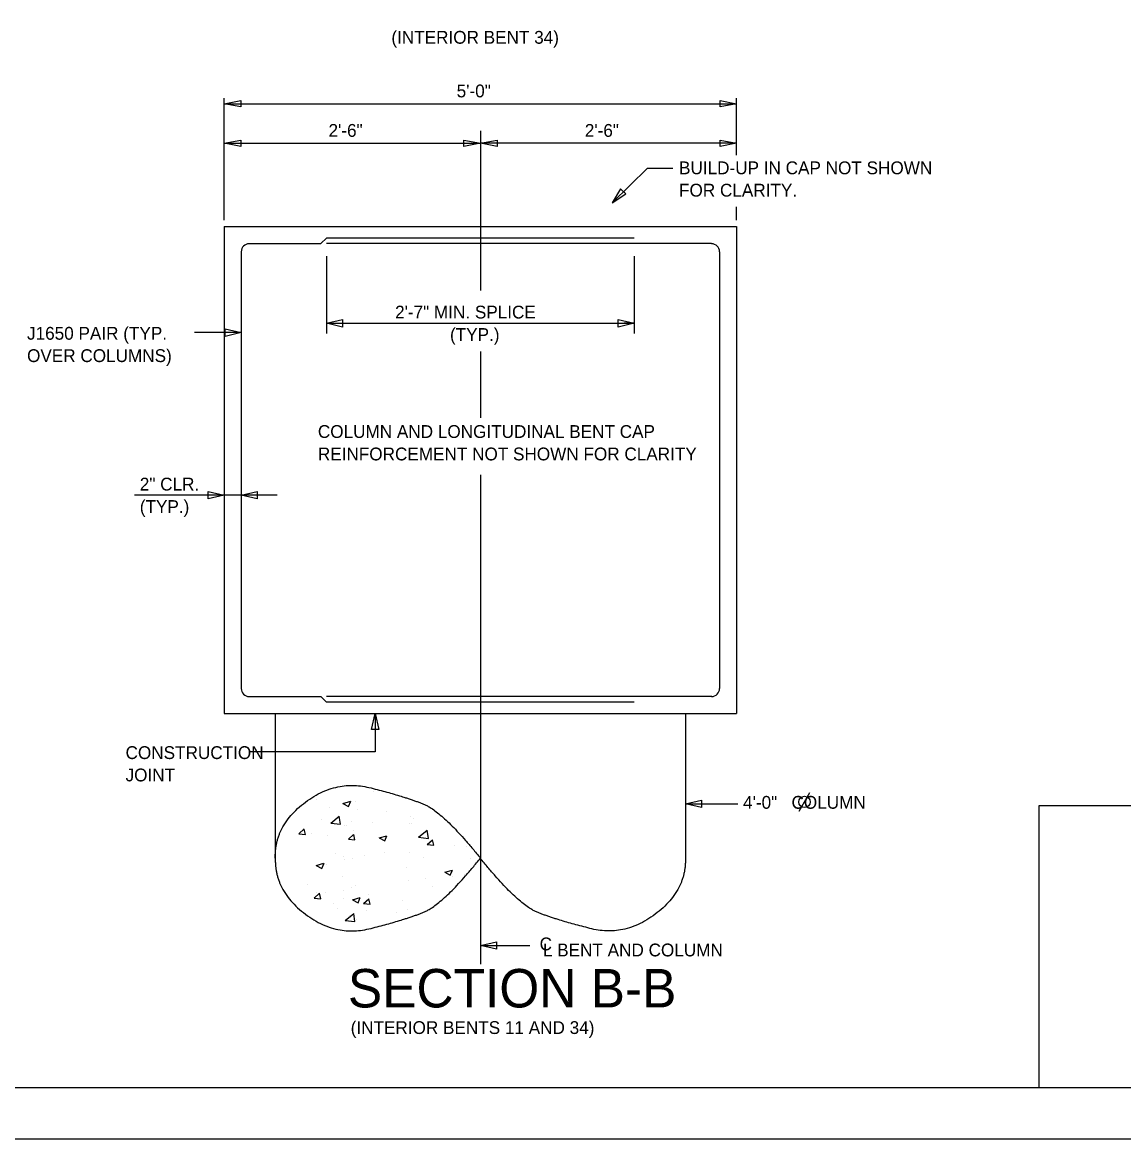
# Model space of a CAD drawing. Extents: x -133.1 to -97, y -1.7 to 20.3.
# Drawn here: x -120.43 to -109.68, y -1.69 to 9.2 of the extents above; entities that cross this region are included whole.
import ezdxf

# ---------------------------------------------------------------- set-up
doc = ezdxf.new("R2010")
doc.units = 0
for name, color, linetype in [('BR_AUTO DIMENSION', 7, 'Continuous'), ('BR_BORDER LINES', 7, 'Continuous'), ('BR_CENTER LINES', 7, 'Continuous'), ('BR_CONCRETE', 7, 'Continuous'), ('BR_REBAR', 7, 'Continuous'), ('BR_TEXT', 7, 'Continuous'), ('Level 31', 7, 'Continuous')]:
    doc.layers.add(name, color=color, linetype=linetype)

msp = doc.modelspace()

# ---------------------------------------------------------------- linework, layer by layer
at = {"layer": 'BR_AUTO DIMENSION'}
for p, q in [((-118.457, 7.268), (-118.457, 8.458)), ((-118.457, 8.403), (-113.457, 8.403)), ((-113.457, 7.903), (-113.457, 8.458)), ((-118.457, 8.018), (-115.957, 8.018)), ((-113.457, 8.018), (-115.957, 8.018)), ((-113.457, 7.268), (-113.457, 7.398)), ((-117.457, 6.918), (-117.457, 6.164)), ((-114.457, 6.918), (-114.457, 6.164)), ((-117.457, 6.262), (-114.457, 6.262)), ((-118.29, 6.171), (-118.744, 6.171)), ((-117.939, 4.586), (-119.331, 4.586)), ((-116.984, 2.455), (-116.984, 2.082)), ((-116.984, 2.082), (-118.208, 2.082)), ((-113.957, 1.576), (-113.445, 1.576)), ((-115.957, 0.192), (-115.474, 0.192))]:
    msp.add_line(p, q, dxfattribs=at)
for points in [[(-118.294, 8.372), (-118.457, 8.403), (-118.294, 8.434)], [(-113.619, 8.434), (-113.457, 8.403), (-113.619, 8.372)], [(-118.294, 7.987), (-118.457, 8.018), (-118.294, 8.05)], [(-116.119, 8.05), (-115.957, 8.018), (-116.119, 7.987)], [(-115.794, 7.987), (-115.957, 8.018), (-115.794, 8.05)], [(-113.619, 8.05), (-113.457, 8.018), (-113.619, 7.987)], [(-114.589, 7.575), (-114.671, 7.437), (-114.537, 7.525)], [(-118.446, 6.207), (-118.29, 6.171), (-118.446, 6.135)], [(-117.301, 6.226), (-117.457, 6.262), (-117.301, 6.298)], [(-114.613, 6.298), (-114.457, 6.262), (-114.613, 6.226)], [(-118.613, 4.622), (-118.457, 4.586), (-118.613, 4.55)], [(-118.134, 4.55), (-118.29, 4.586), (-118.134, 4.622)], [(-117.02, 2.299), (-116.984, 2.455), (-116.948, 2.299)], [(-113.801, 1.54), (-113.957, 1.576), (-113.801, 1.612)], [(-115.801, 0.156), (-115.957, 0.192), (-115.801, 0.228)]]:
    msp.add_lwpolyline(points, close=True, dxfattribs=at)
msp.add_lwpolyline([(-114.671, 7.437), (-114.325, 7.774), (-114.081, 7.774)], dxfattribs=at)
at = {"layer": 'BR_BORDER LINES'}
for p, q in [((-110.507, 1.559), (-105.142, 1.559)), ((-110.507, -1.191), (-110.507, 1.559)), ((-131.308, -1.191), (-97.642, -1.191))]:
    msp.add_line(p, q, dxfattribs=at)
at = {"layer": 'BR_CENTER LINES'}
for p, q in [((-115.957, 8.138), (-115.957, 6.581)), ((-115.957, 5.987), (-115.957, 5.339)), ((-115.957, 4.784), (-115.957, 0.01))]:
    msp.add_line(p, q, dxfattribs=at)
at = {"layer": 'BR_CONCRETE'}
for p, q in [((-118.457, 7.205), (-118.457, 2.455)), ((-118.457, 7.205), (-113.457, 7.205)), ((-113.457, 7.205), (-113.457, 2.455)), ((-118.457, 2.455), (-117.957, 2.455)), ((-117.957, 2.455), (-117.957, 1.014)), ((-117.957, 2.455), (-113.957, 2.455)), ((-113.957, 2.455), (-113.457, 2.455)), ((-113.957, 2.455), (-113.957, 1.015)), ((-117, 1.692), (-117, 1.692)), ((-117.558, 1.622), (-117.558, 1.622)), ((-117.432, 1.541), (-117.432, 1.541)), ((-117.297, 1.578), (-117.222, 1.6)), ((-117.297, 1.578), (-117.244, 1.55)), ((-117.244, 1.55), (-117.222, 1.6)), ((-117.177, 1.595), (-117.177, 1.595)), ((-117.502, 1.422), (-117.502, 1.422)), ((-117.417, 1.388), (-117.333, 1.455)), ((-117.322, 1.376), (-117.333, 1.455)), ((-117.156, 1.515), (-117.156, 1.515)), ((-116.87, 1.496), (-116.87, 1.496)), ((-116.637, 1.451), (-116.637, 1.451)), ((-116.608, 1.432), (-116.608, 1.432)), ((-117.727, 1.282), (-117.675, 1.33)), ((-117.663, 1.277), (-117.675, 1.329)), ((-117.417, 1.388), (-117.322, 1.376)), ((-117.282, 1.363), (-117.282, 1.363)), ((-117.262, 1.368), (-117.262, 1.368)), ((-117.216, 1.403), (-117.216, 1.403)), ((-117.19, 1.317), (-117.19, 1.317)), ((-117.014, 1.39), (-117.014, 1.39)), ((-116.644, 1.384), (-116.644, 1.384)), ((-116.633, 1.38), (-116.633, 1.38)), ((-116.559, 1.25), (-116.476, 1.317)), ((-116.464, 1.238), (-116.476, 1.317)), ((-117.727, 1.282), (-117.663, 1.277)), ((-117.673, 1.294), (-117.673, 1.294)), ((-117.601, 1.284), (-117.601, 1.284)), ((-117.445, 1.264), (-117.445, 1.264)), ((-117.244, 1.229), (-117.193, 1.277)), ((-117.244, 1.229), (-117.18, 1.225)), ((-117.18, 1.225), (-117.192, 1.277)), ((-116.943, 1.242), (-116.868, 1.264)), ((-116.943, 1.242), (-116.89, 1.214)), ((-116.89, 1.214), (-116.868, 1.264)), ((-116.559, 1.25), (-116.464, 1.238)), ((-116.476, 1.177), (-116.424, 1.225)), ((-116.412, 1.173), (-116.424, 1.225)), ((-117.369, 1.091), (-117.369, 1.091)), ((-116.89, 1.103), (-116.89, 1.103)), ((-116.646, 1.102), (-116.646, 1.102)), ((-116.476, 1.177), (-116.412, 1.173)), ((-116.213, 1.173), (-116.213, 1.173)), ((-116.096, 1.161), (-116.096, 1.161)), ((-117.558, 0.973), (-117.483, 0.996)), ((-117.504, 0.945), (-117.482, 0.996)), ((-117.458, 0.986), (-117.458, 0.986)), ((-117.296, 1.062), (-117.296, 1.062)), ((-117.278, 1.034), (-117.278, 1.034)), ((-117.203, 1.04), (-117.203, 1.04)), ((-117.083, 1.073), (-117.083, 1.073)), ((-116.511, 1.054), (-116.511, 1.054)), ((-116.056, 1.037), (-116.056, 1.037)), ((-117.558, 0.973), (-117.504, 0.945)), ((-116.681, 0.954), (-116.681, 0.954)), ((-116.303, 0.907), (-116.228, 0.929)), ((-116.303, 0.907), (-116.25, 0.879)), ((-116.25, 0.878), (-116.228, 0.929)), ((-116.227, 0.871), (-116.227, 0.871)), ((-116.109, 0.884), (-116.109, 0.884)), ((-117.645, 0.787), (-117.645, 0.787)), ((-117.306, 0.87), (-117.306, 0.87)), ((-117.216, 0.762), (-117.216, 0.762)), ((-117.172, 0.775), (-117.172, 0.775)), ((-116.659, 0.825), (-116.659, 0.825)), ((-116.495, 0.844), (-116.495, 0.844)), ((-116.424, 0.771), (-116.424, 0.771)), ((-117.578, 0.655), (-117.527, 0.703)), ((-117.578, 0.666), (-117.578, 0.666)), ((-117.578, 0.655), (-117.514, 0.65)), ((-117.56, 0.706), (-117.56, 0.706)), ((-117.514, 0.65), (-117.527, 0.703)), ((-117.471, 0.709), (-117.471, 0.709)), ((-117.292, 0.733), (-117.292, 0.733)), ((-117.204, 0.638), (-117.129, 0.66)), ((-117.15, 0.61), (-117.129, 0.66)), ((-117.049, 0.687), (-117.049, 0.687)), ((-117.388, 0.604), (-117.388, 0.604)), ((-117.352, 0.554), (-117.352, 0.554)), ((-117.292, 0.647), (-117.292, 0.647)), ((-117.204, 0.638), (-117.15, 0.61)), ((-117.096, 0.602), (-117.044, 0.65)), ((-117.096, 0.602), (-117.031, 0.598)), ((-117.031, 0.598), (-117.044, 0.65)), ((-116.72, 0.628), (-116.72, 0.628)), ((-116.672, 0.547), (-116.672, 0.547)), ((-117.275, 0.438), (-117.191, 0.506)), ((-117.275, 0.438), (-117.18, 0.426)), ((-117.229, 0.485), (-117.229, 0.485)), ((-117.18, 0.426), (-117.191, 0.506)), ((-117.168, 0.446), (-117.168, 0.446)), ((-117.066, 0.535), (-117.066, 0.535)), ((-116.777, 0.515), (-116.777, 0.515))]:
    msp.add_line(p, q, dxfattribs=at)
for points in [[(-117.957, 1.045), (-117.967, 1.361), (-117.368, 1.815), (-116.707, 1.651), (-116.319, 1.496), (-115.957, 1.045)], [(-117.957, 1.045), (-117.967, 0.729), (-117.368, 0.275), (-116.707, 0.439), (-116.319, 0.594), (-115.957, 1.045)], [(-113.957, 1.045), (-113.947, 0.729), (-114.546, 0.275), (-115.206, 0.439), (-115.595, 0.594), (-115.957, 1.045)]]:
    msp.add_open_spline(points, degree=2, dxfattribs=at)
at = {"layer": 'BR_REBAR'}
for p, q in [((-117.512, 7.039), (-117.457, 7.094)), ((-114.457, 7.094), (-117.457, 7.094)), ((-118.212, 7.039), (-117.512, 7.039)), ((-113.701, 7.039), (-117.457, 7.039)), ((-118.29, 6.96), (-118.29, 2.7)), ((-113.624, 6.96), (-113.624, 2.7)), ((-118.212, 2.622), (-117.512, 2.622)), ((-117.512, 2.622), (-117.457, 2.566)), ((-113.7, 2.622), (-117.457, 2.622)), ((-114.457, 2.566), (-117.457, 2.566))]:
    msp.add_line(p, q, dxfattribs=at)
for centre, start, end in [((-118.212, 6.96), 90, 180), ((-113.702, 6.96), 360, 90), ((-118.212, 2.7), 180, 270), ((-113.702, 2.7), 270, 360)]:
    msp.add_arc(centre, 0.0781, start, end, dxfattribs=at)
at = {"layer": 'BR_TEXT'}
for p, q in [((-117.457, 6.262), (-117.38, 6.262)), ((-114.457, 6.262), (-114.554, 6.262)), ((-112.847, 1.503), (-112.742, 1.685))]:
    msp.add_line(p, q, dxfattribs=at)
msp.add_circle((-112.795, 1.594), 0.055, dxfattribs=at)
at = {"layer": 'Level 31'}
msp.add_lwpolyline([(-133.141, -1.691), (-97.141, -1.691), (-97.141, 20.309), (-133.141, 20.309)], close=True, dxfattribs=at)

# ---------------------------------------------------------------- texts
at = {"layer": 'BR_AUTO DIMENSION'}
for s, p in [('(INTERIOR BENT 34)', (-116.825, 8.989)), ('5\'-0"', (-116.188, 8.466)), ('2\'-6"', (-117.438, 8.081)), ('2\'-6"', (-114.938, 8.081)), ('(INTERIOR BENTS 11 AND 34)', (-117.222, -0.67))]:
    msp.add_text(s, height=0.125, dxfattribs=at).set_placement(p)
at = {"layer": 'BR_TEXT'}
for s, p in [('BUILD-UP IN CAP NOT SHOWN', (-114.019, 7.716)), ('FOR CLARITY.', (-114.019, 7.498)), ('2\'-7" MIN. SPLICE', (-116.789, 6.309)), ('J1650 PAIR (TYP.', (-120.379, 6.102)), ('(TYP.)', (-116.253, 6.09)), ('OVER COLUMNS)', (-120.379, 5.884)), ('COLUMN AND LONGITUDINAL BENT CAP', (-117.542, 5.144)), ('REINFORCEMENT NOT SHOWN FOR CLARITY', (-117.542, 4.925)), ('2" CLR.', (-119.279, 4.631)), ('(TYP.)', (-119.279, 4.412)), ('CONSTRUCTION', (-119.418, 2.012)), ('JOINT', (-119.418, 1.794)), ('4\'-0"   COLUMN', (-113.394, 1.527)), ('C', (-115.379, 0.146)), ('L BENT AND COLUMN', (-115.347, 0.087))]:
    msp.add_text(s, height=0.125, rotation=360, dxfattribs=at).set_placement(p)
msp.add_text('SECTION B-B', height=0.375, dxfattribs=at).set_placement((-117.249, -0.411))

doc.saveas('drawing.dxf')
